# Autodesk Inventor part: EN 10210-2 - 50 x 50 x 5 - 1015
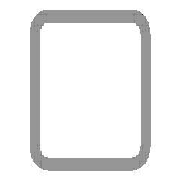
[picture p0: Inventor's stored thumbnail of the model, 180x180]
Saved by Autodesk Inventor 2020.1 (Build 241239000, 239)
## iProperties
_CCFamilyMember: 16
_CCFamilyDisplayName: DIN EN 10210-2 (USAS B17.1 quadratisch) - Rohrleitung — In Klammern angegebene Größen wurden aufgehoben
_FrameMemberDoc: Frame Member File
_Version: 15.0.0
_GetPNFromCC: 1
IsCustomPart: 1
Created: 2019-10
Part Number: EN 10210-2 - 50 x 50 x 5 - 1015
Material: Stahl, weich
Description: Rohrleitung
Document SubType Name: Modeling
Standard: DIN
Designer: lutzd
Standard Revision: 2006-07
Standards Organization: DIN
Language: de-DE
Size Designation: 50 x 50 x 5
Categories: <MemberInstance><Categories><Category DisplayName="Profile" InternalName="089c4875-fa83-4c05-b084-43b9cc11f5ed" Mnemonic="GRDR"><CategoryParameter DisplayName="
Stock Number: 50 x 50 x 5
Mass: 6957.24 g
Surface Area: 3453.64 cm^2
Volume: 886.272 cm^3
Density: 7.85 g/cm^3
Appearance: Halbpoliert
G_L: 1015,000 mm
G_W: 50,000 mm
G_H: 50,000 mm
Dimensions: 50x50x1015 mm
Mass: 6,957 kg
DocNumber: ADSK-014103
Folder: .
Title: Profil-Bauteil
Author: lutzd
Revision Number: -
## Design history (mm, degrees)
node "Startebene"
node "Endebene"
sketch "Skizze"
  geometry: L1 (-25, -17.5)-(-25, 17.5); L2 (-17.5, 25)-(17.5, 25); L3 (25, 17.5)-(25, -17.5); L4 (17.5, -25)-(-17.5, -25); L5 (-15, 20)-(15, 20); L6 (20, 15)-(20, -15); L7 (15, -20)-(-15, -20); L8 (-20, -15)-(-20, 15); L9 (0, 37.175)-(0, -37.175) reference; L10 (-37.175, 0)-(37.175, 0) reference; A1 r 7.5 centre (-17.5, -17.5) between (-25, -17.5) and (-17.5, -25); A2 r 7.5 centre (-17.5, 17.5) between (-17.5, 25) and (-25, 17.5); A3 r 7.5 centre (17.5, 17.5) between (25, 17.5) and (17.5, 25); A4 r 7.5 centre (17.5, -17.5) between (17.5, -25) and (25, -17.5); A5 r 5 centre (-15, -15) between (-20, -15) and (-15, -20); A6 r 5 centre (-15, 15) between (-15, 20) and (-20, 15); A7 r 5 centre (15, 15) between (20, 15) and (15, 20); A8 r 5 centre (15, -15) between (15, -20) and (20, -15)
  constraints: 16 end point, 16 point on circle, 16 tangent, 8 centre point, 6 equal radius, 4 parallel, 2 perpendicular, 2 other
  dimensions: "d7" = 7.5 radius of A1 (= G_IR); "d10" = 50 distance between parallel lines of L2 L4 (= G_H); "d11" = 50 distance between parallel lines of L1 L3 (= G_W); "d12" = 5 distance between parallel lines of L3 L6 (= G_T); "d15" = 25 distance between parallel lines of L2 L10 (= 0.5 x d10); "d16" = 25 distance between parallel lines of L9 L3 (= 0.5 x d11); "d19" = 5 radius of A5 (= G_T); "d20" = 5 distance between parallel lines of L4 L7 (= G_T)
extrude "Körper" new body sketch "Skizze" stored distance "d3" = 1015 (= G_L); taper "d4" = 0 deg
node "Driven Length"
  sketch "Sketch3"
    geometry: L1 (0, 0)-(10, 0) reference
    constraints: 2 end point, 1 horizontal
  workplane "Work Plane3"
  sketch "Sketch4"
    geometry: L1 (-2, 35)-(12, 35) reference; L2 (-2, 1050)-(12, 1050) reference
    dimensions: "d18" = 1015 distance between parallel lines of L1 L2 (derived)
body "Solid1"
other parameters: "G_W" = 50 [user parameter; used in 1 equation term], "G_H" = 50 [user parameter; used in 1 equation term], "G_T" = 5 [user parameter; used in 3 equation terms], "G_IR" = 7.5 [user parameter; used in 1 equation term], "G_L" = 1015 (= d18) [user parameter; used in 1 equation term], "G_OFFSET_START" = -35 [user parameter; used in 1 equation term], "G_OFFSET_END" = 0 [user parameter; used in 1 equation term], "d13" = 35 (= -G_OFFSET_START), "d17" = 90 deg
